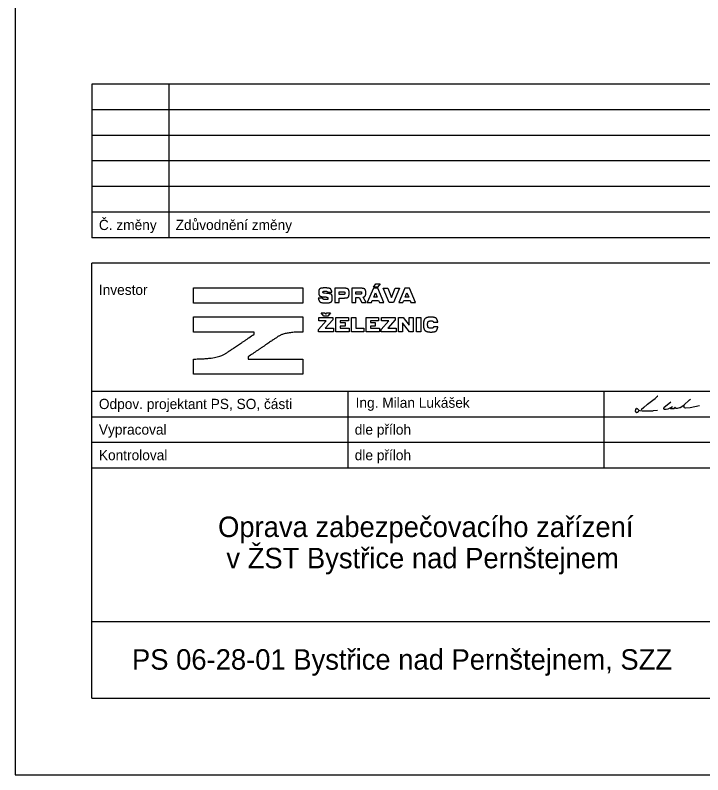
# Model space of a CAD drawing. Extents: x -790261 to -790051, y -987072 to -986775.
# Drawn here: x -790260.6 to -790126.2, y -987071.6 to -986923.1 of the extents above; entities that cross this region are included whole.
import ezdxf

# ---------------------------------------------------------------- set-up
doc = ezdxf.new("R2010")
doc.units = 0
for name, color, linetype in [('Deska žb', 7, 'Continuous'), ('logo_sprava_zeleznic', 7, 'Continuous'), ('Nová vrstva (0)', 7, 'Continuous'), ('Ramečky', 7, 'Continuous'), ('Rámečky-tisk', 7, 'Continuous'), ('Text', 7, 'Continuous'), ('Text barevný', 7, 'Continuous')]:
    doc.layers.add(name, color=color, linetype=linetype)

# ---------------------------------------------------------------- blocks, each defined once
blk = doc.blocks.new('Lukášek')
at = {"layer": 'Deska žb'}
for points in [[(-800, 511), (-947, 387)], [(-658, 623), (-799, 512)], [(-538, 757), (-656, 625)], [(-526, 763), (-532, 761)], [(-502, 743), (-503, 750)], [(1060, 236), (1392, 554)], [(1393, 555), (1452, 601)], [(-1810, -20), (-1764, 37)], [(-1741, 39), (-1734, 34)], [(-1733, 32), (-1676, -31)], [(-1334, 99), (-1493, -40)], [(-1120, 270), (-1334, 99)], [(-949, 386), (-1119, 271)], [(-146, 58), (-146, 41)], [(-146, 38), (-141, 12)], [(277, 422), (-140, 71)], [(0, 0), (116, 16)], [(120, 17), (203, 49)], [(205, 50), (283, 92)], [(244, 59), (250, 49)], [(261, 42), (331, 30)], [(284, 93), (373, 148)], [(335, 30), (465, 39)], [(476, 45), (519, 96)], [(546, 94), (559, 68)], [(574, 60), (681, 63)], [(685, 63), (829, 98)], [(833, 100), (1057, 233)], [(1056, 231), (1056, 130)], [(1058, 121), (1075, 95)], [(1086, 88), (1147, 79)], [(1150, 79), (1434, 92)], [(1437, 93), (1997, 211)], [(-1825, -119), (-1813, -28)], [(-1809, -179), (-1825, -126)], [(-1757, -200), (-1797, -190)], [(-1700, -189), (-1749, -201)], [(-1634, -152), (-1695, -187)], [(-1672, -34), (-1636, -56)], [(-1633, -57), (-1570, -82)], [(-1567, -83), (-1418, -106)], [(-1415, -106), (-1252, -106), (-1041, -106)], [(-1040, -106), (-770, -93)], [(-769, -92), (-512, -66)], [(-127, -2), (-88, -6)], [(-85, -7), (-1, 0)]]:
    blk.add_lwpolyline(points, dxfattribs=at)
for centre, start, end in [((-789, 499), 128.3333, 130.1792), ((-669, 636), 308.3333, 317.9357), ((-525, 746), 113.9625, 137.9357), ((-519, 748), 6.3402, 113.9625), ((1403, 542), 127.875, 133.8427), ((-1751, 26), 50.1944, 140.7106), ((-1745, 21), 41.9872, 50.1944), ((-1324, 86), 128.6598, 131.1859), ((-1110, 257), 123.9436, 128.6598), ((-958, 399), 303.9436, 310.1792), ((-129, 58), 130.156, 180), ((-129, 41), 180, 189.4623), ((-125, 15), 189.4623, 262.875), ((-2, 16), 274.3987, 277.9072), ((114, 32), 277.9072, 291.0375), ((197, 64), 291.0375, 298.4429), ((264, 58), 210.9638, 260.5377), ((275, 107), 298.4429, 302.1957), ((334, 46), 260.5377, 274.0856), ((463, 55), 274.0856, 320.4403), ((531, 86), 27.8973, 140.4403), ((574, 76), 207.8973, 271.5911), ((681, 79), 271.5911, 283.7363), ((825, 114), 283.7363, 300.7189), ((1072, 130), 180, 212.4712), ((1049, 247), 300.7189, 313.8427), ((1089, 104), 212.4712, 261.8699), ((1149, 96), 261.8699, 272.6324), ((1433, 109), 272.6324, 281.9566), ((-1809, -121), 172.4054, 196.6992), ((-1797, -30), 140.7106, 172.4054), ((-1793, -175), 196.6992, 255.9638), ((-1753, -184), 255.9638, 283.2405), ((-1703, -173), 283.2405, 300.0686), ((-1664, -20), 221.9872, 239.7436), ((-1627, -41), 239.7436, 248.1986), ((-1564, -67), 248.1986, 261.3475), ((-1415, -89), 261.3475, 270), ((-1041, -89), 270, 272.7927), ((-771, -76), 272.7927, 275.856), ((-86, 10), 262.875, 274.3987)]:
    blk.add_arc(centre, 16.5, start, end, dxfattribs=at)

msp = doc.modelspace()

# ---------------------------------------------------------------- linework, layer by layer
at = {"layer": 'logo_sprava_zeleznic'}
for p, q in [((-790190.56, -986976.26), (-790190.12, -986975.6)), ((-790189.78, -986976.26), (-790190.56, -986976.26)), ((-790190.12, -986975.6), (-790189.3, -986975.6)), ((-790189.3, -986975.6), (-790189.78, -986976.26)), ((-790188.7, -986976.48), (-790187.76, -986976.48)), ((-790187.49, -986979.29), (-790188.7, -986976.48)), ((-790187.76, -986976.48), (-790187.05, -986978.28)), ((-790187.05, -986978.28), (-790186.34, -986976.48)), ((-790185.49, -986976.48), (-790186.64, -986979.29)), ((-790186.34, -986976.48), (-790185.49, -986976.48)), ((-790200.51, -986978.45), (-790201.36, -986978.45)), ((-790199.76, -986977.48), (-790200.15, -986977.45)), ((-790199.51, -986977.23), (-790198.69, -986977.23)), ((-790186.64, -986979.29), (-790187.49, -986979.29)), ((-790200.29, -986981.96), (-790200.83, -986981.28)), ((-790200.83, -986981.28), (-790200.14, -986981.28)), ((-790200.14, -986981.28), (-790199.91, -986981.56)), ((-790199.91, -986981.56), (-790199.68, -986981.28)), ((-790199.68, -986981.28), (-790198.97, -986981.28)), ((-790198.97, -986981.28), (-790199.53, -986981.96)), ((-790201.3, -986984.53), (-790199.84, -986982.86)), ((-790201.26, -986982.17), (-790198.55, -986982.17)), ((-790201.26, -986982.86), (-790201.26, -986982.17)), ((-790199.84, -986982.86), (-790201.26, -986982.86)), ((-790199.53, -986981.96), (-790200.29, -986981.96)), ((-790198.55, -986982.63), (-790200.02, -986984.29)), ((-790198.55, -986982.17), (-790198.55, -986982.63)), ((-790197.92, -986982.17), (-790195.49, -986982.17)), ((-790197.92, -986984.99), (-790197.92, -986982.17)), ((-790195.49, -986982.83), (-790197.1, -986982.83)), ((-790197.1, -986982.83), (-790197.1, -986983.2)), ((-790195.49, -986982.17), (-790195.49, -986982.83)), ((-790194.86, -986982.17), (-790194.05, -986982.17)), ((-790194.86, -986984.99), (-790194.86, -986982.17)), ((-790194.05, -986982.17), (-790194.05, -986984.28)), ((-790191.99, -986982.17), (-790189.57, -986982.17)), ((-790191.99, -986984.99), (-790191.99, -986982.17)), ((-790189.57, -986982.83), (-790191.18, -986982.83)), ((-790191.18, -986982.83), (-790191.18, -986983.2)), ((-790189.57, -986982.17), (-790189.57, -986982.83)), ((-790189.07, -986984.53), (-790187.61, -986982.86)), ((-790189.03, -986982.17), (-790186.33, -986982.17)), ((-790189.03, -986982.86), (-790189.03, -986982.17)), ((-790187.61, -986982.86), (-790189.03, -986982.86)), ((-790186.33, -986982.63), (-790187.8, -986984.29)), ((-790186.33, -986982.17), (-790186.33, -986982.63)), ((-790185.69, -986982.17), (-790184.78, -986982.17)), ((-790185.69, -986984.99), (-790185.69, -986982.17)), ((-790184.78, -986982.17), (-790183.63, -986983.68)), ((-790183.63, -986983.68), (-790183.63, -986982.17)), ((-790183.63, -986982.17), (-790182.85, -986982.17)), ((-790182.85, -986982.17), (-790182.85, -986984.99)), ((-790200.02, -986984.29), (-790198.39, -986984.29)), ((-790198.39, -986984.29), (-790198.39, -986984.99)), ((-790197.1, -986983.2), (-790196.14, -986983.2)), ((-790196.14, -986983.87), (-790197.1, -986983.87)), ((-790197.1, -986983.87), (-790197.1, -986984.3)), ((-790197.1, -986984.3), (-790195.34, -986984.3)), ((-790196.14, -986983.2), (-790196.14, -986983.87)), ((-790195.34, -986984.3), (-790195.34, -986984.99)), ((-790194.05, -986984.28), (-790192.47, -986984.28)), ((-790192.47, -986984.28), (-790192.47, -986984.99)), ((-790191.18, -986983.2), (-790190.22, -986983.2)), ((-790190.22, -986983.87), (-790191.18, -986983.87)), ((-790191.18, -986983.87), (-790191.18, -986984.3)), ((-790191.18, -986984.3), (-790189.41, -986984.3)), ((-790190.22, -986983.2), (-790190.22, -986983.87)), ((-790189.41, -986984.3), (-790189.41, -986984.99)), ((-790187.8, -986984.29), (-790186.16, -986984.29)), ((-790186.16, -986984.29), (-790186.16, -986984.99)), ((-790183.53, -986984.99), (-790184.89, -986983.26)), ((-790184.89, -986983.26), (-790184.89, -986984.99)), ((-790178.84, -986983.12), (-790178.01, -986983.12)), ((-790178.01, -986984.05), (-790178.83, -986984.05)), ((-790201.3, -986984.99), (-790201.3, -986984.53)), ((-790198.39, -986984.99), (-790201.3, -986984.99)), ((-790195.34, -986984.99), (-790197.92, -986984.99)), ((-790192.47, -986984.99), (-790194.86, -986984.99)), ((-790189.41, -986984.99), (-790191.99, -986984.99)), ((-790189.07, -986984.99), (-790189.07, -986984.53)), ((-790186.16, -986984.99), (-790189.07, -986984.99)), ((-790184.89, -986984.99), (-790185.69, -986984.99)), ((-790182.85, -986984.99), (-790183.53, -986984.99))]:
    msp.add_line(p, q, dxfattribs=at)
for points in [[(-790225.73, -986976.4), (-790204.41, -986976.4), (-790204.41, -986979.38), (-790225.73, -986979.38)], [(-790191.8, -986979.29), (-790190.98, -986979.29), (-790190.82, -986978.89), (-790189.57, -986978.89), (-790189.41, -986979.29), (-790188.53, -986979.29), (-790189.73, -986976.48), (-790190.6, -986976.48)], [(-790185.65, -986979.29), (-790184.83, -986979.29), (-790184.66, -986978.89), (-790183.42, -986978.89), (-790183.26, -986979.29), (-790182.38, -986979.29), (-790183.57, -986976.48), (-790184.45, -986976.48)], [(-790190.19, -986977.39), (-790189.85, -986978.23), (-790190.54, -986978.23)], [(-790184.04, -986977.39), (-790183.7, -986978.23), (-790184.39, -986978.23)], [(-790182.16, -986982.17), (-790181.35, -986982.17), (-790181.35, -986984.99), (-790182.16, -986984.99)]]:
    msp.add_lwpolyline(points, close=True, dxfattribs=at)
for points in [[(-790196.38, -986976.48), (-790198.11, -986976.48), (-790198.11, -986979.29), (-790197.3, -986979.29), (-790197.3, -986978.39), (-790196.38, -986978.39)], [(-790193.12, -986976.48), (-790194.84, -986976.48), (-790194.84, -986979.29), (-790194.03, -986979.29), (-790194.03, -986978.31), (-790193.39, -986978.31), (-790192.84, -986979.29), (-790191.98, -986979.29), (-790192.59, -986978.22)], [(-790196.48, -986977.69), (-790197.3, -986977.69), (-790197.3, -986977.17), (-790196.48, -986977.17)], [(-790193.22, -986977.64), (-790194.03, -986977.64), (-790194.03, -986977.16), (-790193.22, -986977.16)], [(-790213.87, -986985.46), (-790213.87, -986985.04), (-790225.73, -986985.04), (-790225.73, -986982.07), (-790204.41, -986982.07), (-790204.41, -986985.04)], [(-790215.1, -986989.91), (-790215.1, -986990.32), (-790204.41, -986990.32), (-790204.41, -986993.3), (-790225.73, -986993.3), (-790225.73, -986990.32), (-790225.71, -986990.32)]]:
    msp.add_lwpolyline(points, dxfattribs=at)
for centre, radius, start, end in [((-790201.9, -986999.14), 21.01, 84.2634, 85.3384), ((-790251.18, -986932.6), 64.69, 304.0901, 305.2133), ((-789914.63, -987426.54), 530.02, 124.292, 124.5333)]:
    msp.add_arc(centre, radius, start, end, dxfattribs=at)
for points in [[(-790200.05, -986976.42), (-790200.77, -986976.42), (-790201.29, -986976.71), (-790201.29, -986977.28)], [(-790198.69, -986977.23), (-790198.77, -986976.87), (-790199.09, -986976.42), (-790200.05, -986976.42)], [(-790195.34, -986977.43), (-790195.34, -986976.8), (-790195.73, -986976.48), (-790196.38, -986976.48)], [(-790192.08, -986977.4), (-790192.08, -986976.79), (-790192.49, -986976.48), (-790193.12, -986976.48)], [(-790201.36, -986978.45), (-790201.29, -986978.84), (-790200.93, -986979.34), (-790199.92, -986979.34)], [(-790201.29, -986977.28), (-790201.29, -986977.83), (-790200.87, -986978.14), (-790200.19, -986978.2)], [(-790199.92, -986978.71), (-790200.28, -986978.71), (-790200.46, -986978.57), (-790200.51, -986978.45)], [(-790200.46, -986977.24), (-790200.46, -986977.12), (-790200.3, -986977.06), (-790200.05, -986977.06)], [(-790200.15, -986977.45), (-790200.35, -986977.43), (-790200.46, -986977.36), (-790200.46, -986977.24)], [(-790200.05, -986977.06), (-790199.73, -986977.06), (-790199.55, -986977.17), (-790199.51, -986977.23)], [(-790199.92, -986979.34), (-790199.08, -986979.34), (-790198.63, -986979), (-790198.63, -986978.4)], [(-790199.47, -986978.46), (-790199.47, -986978.61), (-790199.6, -986978.71), (-790199.92, -986978.71)], [(-790199.8, -986978.23), (-790199.6, -986978.26), (-790199.47, -986978.31), (-790199.47, -986978.46)], [(-790198.63, -986978.4), (-790198.63, -986977.79), (-790199.03, -986977.53), (-790199.76, -986977.48)], [(-790196.48, -986977.17), (-790196.27, -986977.17), (-790196.17, -986977.26), (-790196.17, -986977.43)], [(-790196.17, -986977.43), (-790196.17, -986977.59), (-790196.27, -986977.69), (-790196.48, -986977.69)], [(-790196.38, -986978.39), (-790195.73, -986978.39), (-790195.34, -986978.06), (-790195.34, -986977.43)], [(-790193.22, -986977.16), (-790193.02, -986977.16), (-790192.91, -986977.23), (-790192.91, -986977.4)], [(-790192.91, -986977.4), (-790192.91, -986977.55), (-790193.02, -986977.64), (-790193.22, -986977.64)], [(-790192.59, -986978.22), (-790192.27, -986978.08), (-790192.08, -986977.8), (-790192.08, -986977.4)], [(-790179.36, -986982.13), (-790180.22, -986982.13), (-790180.82, -986982.73), (-790180.82, -986983.58)], [(-790180, -986983.58), (-790180, -986983.18), (-790179.76, -986982.85), (-790179.36, -986982.85)], [(-790178.01, -986983.12), (-790178.06, -986982.8), (-790178.4, -986982.13), (-790179.36, -986982.13)], [(-790179.36, -986982.85), (-790179.02, -986982.85), (-790178.88, -986983.05), (-790178.84, -986983.12)], [(-790180.82, -986983.58), (-790180.82, -986984.43), (-790180.22, -986985.04), (-790179.36, -986985.04)], [(-790179.36, -986984.31), (-790179.76, -986984.31), (-790180, -986983.99), (-790180, -986983.58)], [(-790179.36, -986985.04), (-790178.37, -986985.04), (-790178.05, -986984.31), (-790178.01, -986984.05)], [(-790178.83, -986984.05), (-790178.87, -986984.12), (-790179.02, -986984.31), (-790179.36, -986984.31)], [(-790204.41, -986985.04), (-790207.9, -986985.04), (-790210.38, -986986.71), (-790213.25, -986988.65)], [(-790225.71, -986990.32), (-790221.06, -986990.31), (-790218.08, -986988.3), (-790214.92, -986986.18)]]:
    msp.add_open_spline(points, degree=2, dxfattribs=at)
at = {"layer": 'Ramečky'}
for p, q in [((-790065.59, -986936.6), (-790245.59, -986936.6)), ((-790245.59, -986936.6), (-790245.59, -986966.6)), ((-790230.59, -986936.6), (-790230.59, -986966.6)), ((-790095.59, -986941.6), (-790245.59, -986941.6)), ((-790095.59, -986946.6), (-790245.59, -986946.6)), ((-790095.59, -986951.6), (-790245.59, -986951.6)), ((-790095.59, -986956.6), (-790245.59, -986956.6)), ((-790095.59, -986961.6), (-790245.59, -986961.6)), ((-790065.59, -986966.6), (-790245.59, -986966.6)), ((-790065.59, -986971.6), (-790245.59, -986971.6)), ((-790245.59, -987056.6), (-790245.59, -986971.6)), ((-790245.59, -986996.6), (-790115.59, -986996.6)), ((-790245.59, -987001.6), (-790115.59, -987001.6)), ((-790245.59, -987006.6), (-790115.59, -987006.6)), ((-790245.59, -987011.6), (-790115.59, -987011.6)), ((-790245.59, -987041.6), (-790065.59, -987041.6)), ((-790245.59, -987056.6), (-790065.59, -987056.6))]:
    msp.add_line(p, q, dxfattribs=at)
for points in [[(-790195.59, -986996.6), (-790195.59, -987011.6)], [(-790145.59, -986996.6), (-790145.59, -987011.6)]]:
    msp.add_lwpolyline(points, dxfattribs=at)
at = {"layer": 'Rámečky-tisk'}
msp.add_line((-790260.59, -986774.6), (-790260.59, -987071.6), dxfattribs=at)
msp.add_lwpolyline([(-790260.59, -987071.6), (-790050.59, -987071.6), (-790050.59, -986774.6)], dxfattribs=at)

# ---------------------------------------------------------------- block references
at = {"layer": 'Nová vrstva (0)', "xscale": 0.00327555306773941, "yscale": 0.00327555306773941}
msp.add_blockref('Lukášek', (-790133.4, -987000.11), dxfattribs=at)

# ---------------------------------------------------------------- texts
at = {"layer": 'Text'}
for s, p in [('Č. změny', (-790244.24, -986965.1)), ('Zdůvodnění změny', (-790229.24, -986965.1)), ('Investor', (-790244.24, -986977.78)), ('Ing. Milan Lukášek', (-790194.07, -986999.85)), ('Odpov. projektant PS, SO, části', (-790244.24, -987000.1)), ('Vypracoval', (-790244.24, -987005.1)), ('dle příloh', (-790194.24, -987005.1)), ('Kontroloval', (-790244.24, -987010.1)), ('dle příloh', (-790194.24, -987010.1))]:
    msp.add_text(s, height=2, dxfattribs=at).set_placement(p)
at = {"layer": 'Text barevný'}
for s, p in [('Oprava zabezpečovacího zařízení', (-790220.95, -987025.12)), ('v ŽST Bystřice nad Pernštejnem', (-790219.33, -987031.23)), ('PS 06-28-01 Bystřice nad Pernštejnem, SZZ', (-790237.77, -987051.05))]:
    msp.add_text(s, height=4, dxfattribs=at).set_placement(p)

doc.saveas('drawing.dxf')
